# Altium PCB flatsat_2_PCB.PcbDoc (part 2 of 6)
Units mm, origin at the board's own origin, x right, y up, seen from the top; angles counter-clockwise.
Board outline 400 x 250 mm, 4 copper layers (Top Layer, FlatSat GND, FlatSat VCC, Bottom Layer), stack 2.102 mm thick; 196 components, 289 nets, 1724 pads, 1139 vias.
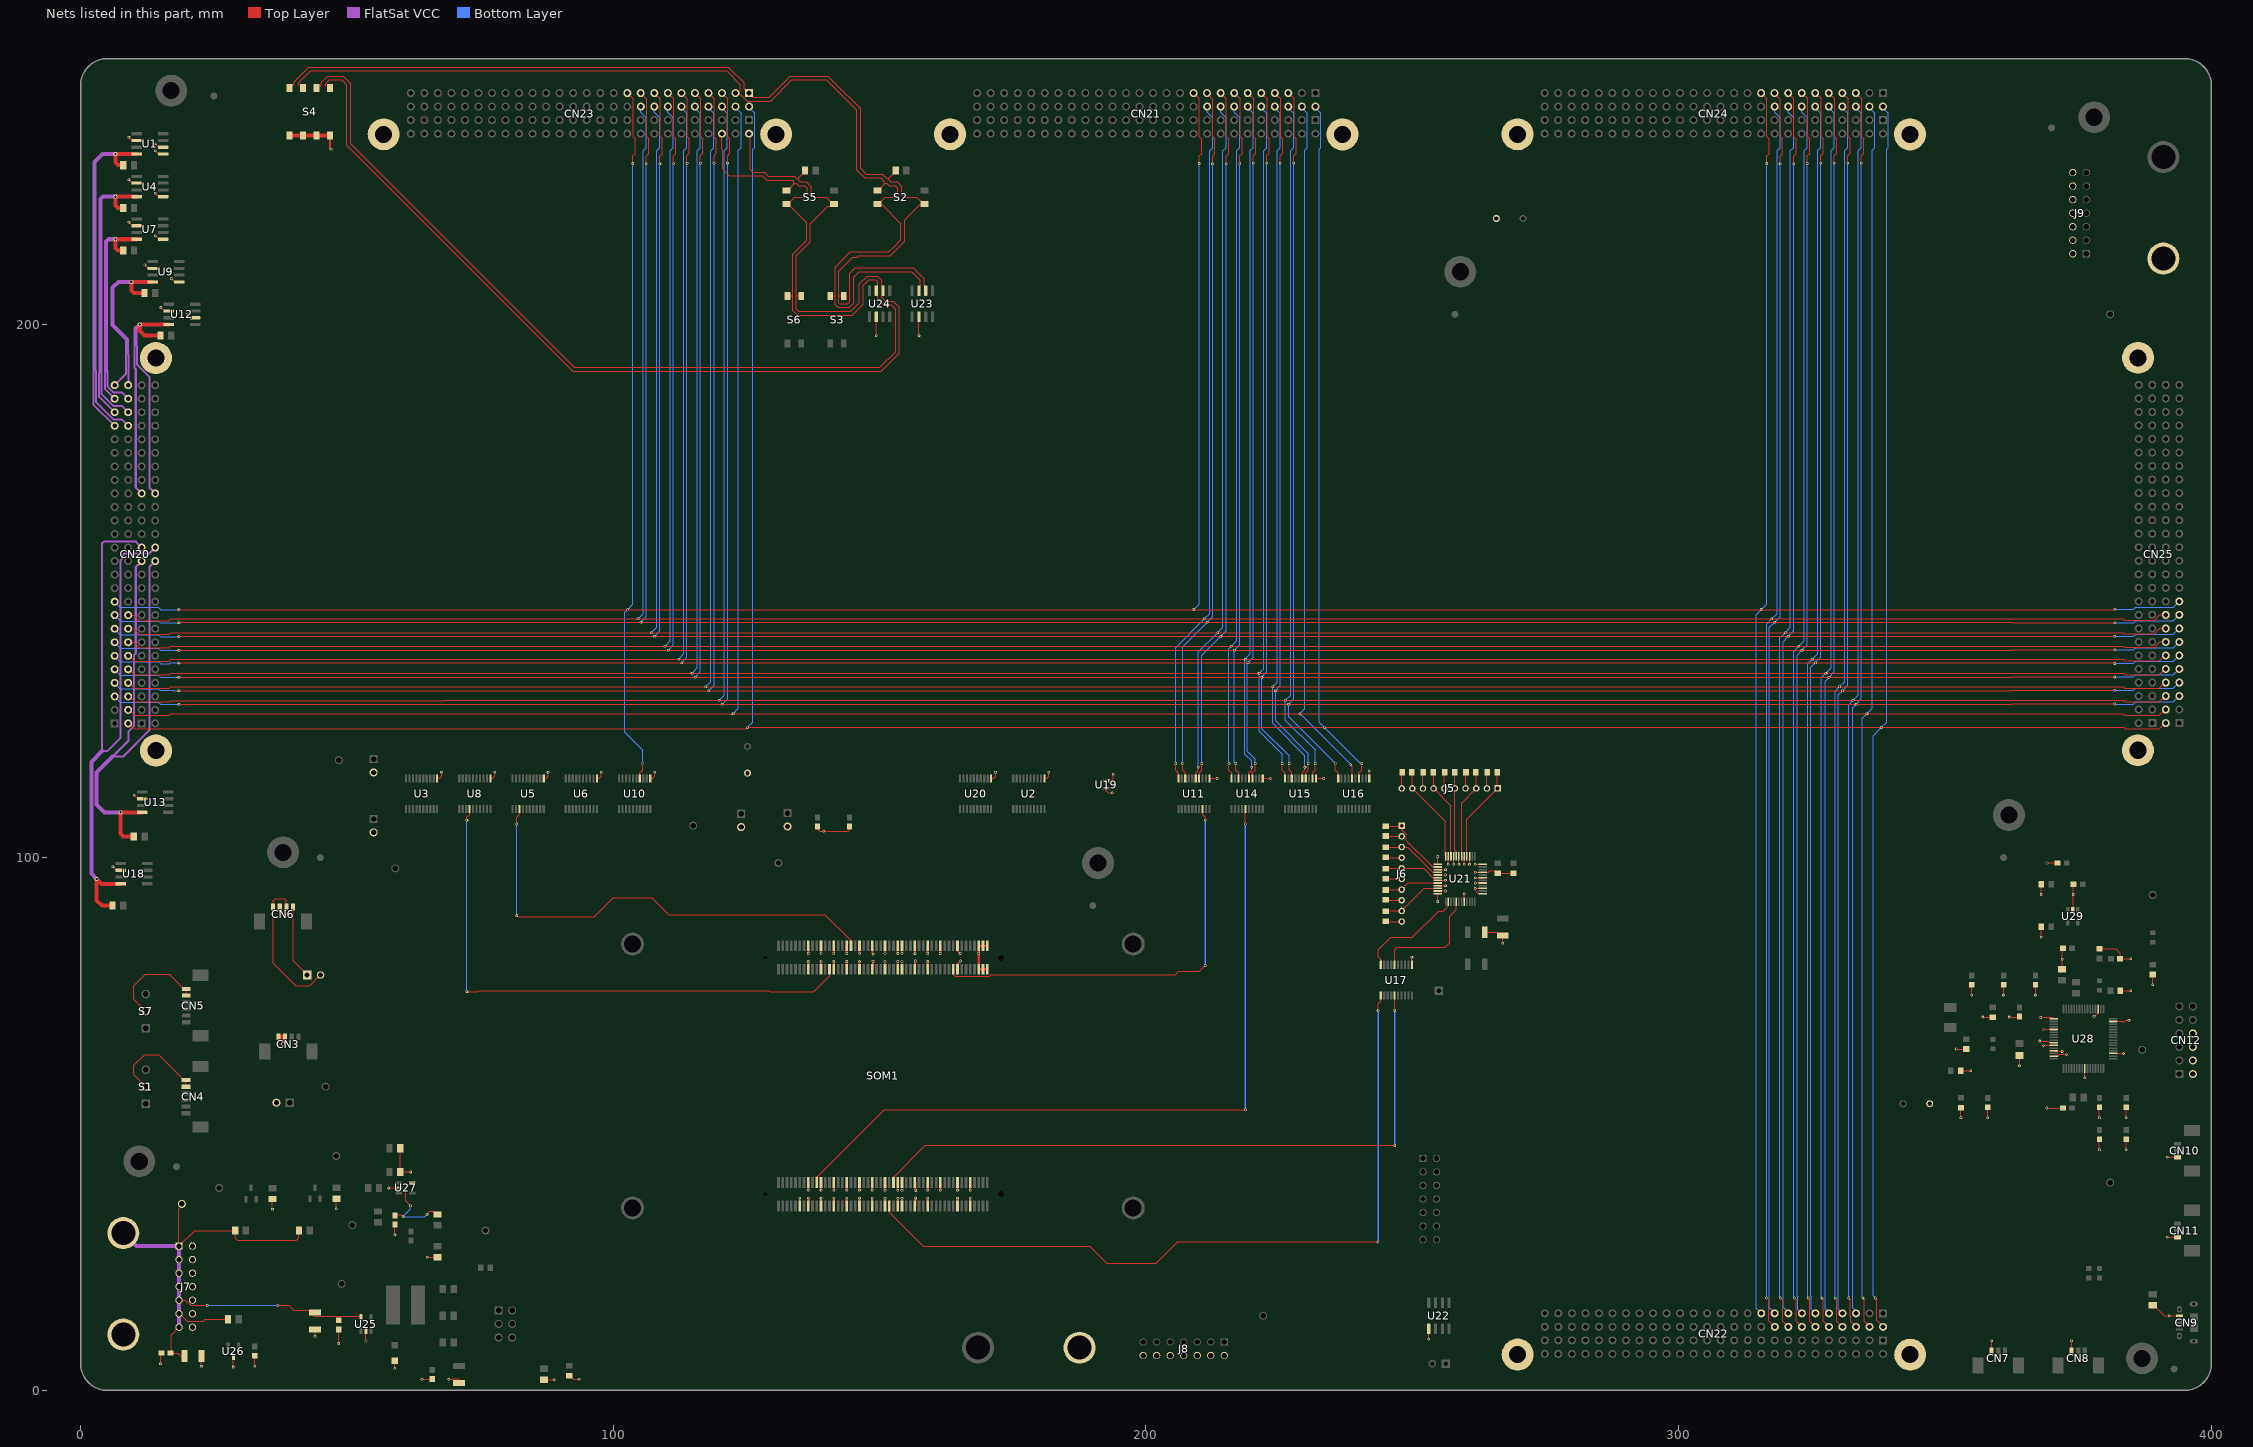
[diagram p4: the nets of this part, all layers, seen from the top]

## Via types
v1: diameter 0.508, hole 0.3, Top Layer to Bottom Layer, tented both sides, 1073 vias
v2: diameter 0.762, hole 0.45, Top Layer to Bottom Layer, tented both sides, 66 vias

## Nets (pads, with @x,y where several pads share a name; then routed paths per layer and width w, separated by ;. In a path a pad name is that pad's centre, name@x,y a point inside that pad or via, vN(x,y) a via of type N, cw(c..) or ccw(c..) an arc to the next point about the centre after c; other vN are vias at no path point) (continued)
5V: C1.1 C2.1 C6.1 C7.1 C9.2 CN1.1 J7.1 J7.3 J7.5 J7.7 J7.9 J7.11 J7.13 R2.2 R7.2 R10.2 R14.2 SOM1.JX1-57 SOM1.JX1-58 SOM1.JX1-59 SOM1.JX1-60 SOM1.JX2-12 SOM1.JX2-57 SOM1.JX2-58 SOM1.JX2-59 SOM1.JX2-60 TP4.1 U25.5 U27.5 | length 146.4
  Top Layer w0.203: J7.13@18.46,11.84 17,10.38 17,7.075 16.925,7 18.257,7 18.843,6.414 19.456,6.414 C2.1@19.468,6.427 ; J7.11@18.46,14.38 18.62,14.38 20,13 23,13 23.35,13.35 R14.2@27.654,13.35 ; J7.9@18.46,16.92 19.636,16.92 20.621,15.935 v1(23.754,15.935) ; TP4.1@19,35 19,34.649 18.46,34.109 J7.1@18.46,27.08 21.38,30 R2.2@28.984,30 28.984,28.596 29.415,28.165 40.501,28.165 40.984,28.648 R7.2@40.984,30 ; v1(36.935,15.935) 39.065,15.935 40,15 42.85,15 43.35,14.5 43.677,14.518 43.675,14.517 43.675,14.036 43.811,13.9 48.445,13.9 ; C6.1@48.445,13.15 48.445,13.9 ; U25.5@52.612,13.695 52.612,13.71 52.422,13.9 48.445,13.9 ; C9.2@59,32.85 59.075,32.925 60.196,32.925 v1(60.499,32.622) ; v1(61.917,34.653) 61,35.571 61,38.005 61.945,38.95 U27.5@62.255,38.95 ; v1(65,33) 65.575,33.575 66.175,33.575 66.236,33.514 66.502,33.514 R10.2@67,33.016 ; SOM1.JX2-12@135,34.6 v1(135,36.06) ; SOM1.JX2-58@153.4,34.6 v1(153.4,36.06) ; v1(153.4,37.54) SOM1.JX2-57@153.4,39 ; SOM1.JX1-58@153.4,79.05 v1(153.4,80.51) ; v1(153.4,81.99) SOM1.JX1-57@153.4,83.45 ; SOM1.JX2-60@154.2,34.6 v1(154.2,36.06) ; v1(154.2,37.54) SOM1.JX2-59@154.2,39 ; SOM1.JX1-60@154.2,79.05 v1(154.2,80.51) ; v1(154.2,81.99) SOM1.JX1-59@154.2,83.45
  FlatSat VCC w0.762: CN1.1@8,29.525 10.445,27.08 J7.1@18.46,27.08 J7.3@18.46,24.54 J7.5@18.46,22 J7.7@18.46,19.46 J7.9@18.46,16.92 J7.11@18.46,14.38 J7.13@18.46,11.84
  Bottom Layer w0.203: v1(23.754,15.935) v1(36.935,15.935) ; v1(61.917,34.653) 61.917,34.041 v1(60.499,32.622) 64.622,32.622 v1(65,33)
+RBF: CN6.2 CN6.4 J3.1 | length 17.6
  Top Layer w0.203: CN6.2@37.375,90.745 37.375,89.745 37.75,89.37 39.493,89.37 39.875,89.752 ; CN6.4@39.875,90.745 39.875,89.752 ; J3.1@42.5,78 39.875,80.625 39.875,89.752
-RBF: CN6.1 CN6.3 J3.2 | length 27.1
  Top Layer w0.203: CN6.3@38.625,90.745 38.625,91.957 38.286,92.296 36.517,92.296 36.125,91.904 CN6.1@36.125,90.745 36.125,80.225 40.35,76 43,76 J3.2@45,78
CAN_CHN_1_N: CN23.1 R16.1 S2.2B S3.2B S4.1B U23.6 | length 201.3
  Top Layer w0.203: S4.1B@39.19,244.45 39.19,244.65 39.638,245.098 39.985,245.098 40.104,245.217 40.104,245.68 42.855,248.431 121.575,248.431 124.566,245.44 124.566,244.307 124.685,244.188 124.832,244.188 CN23.1@125.48,243.54 126.128,242.892 126.128,242.86 126.247,242.741 129.271,242.741 133.241,246.711 140.289,246.711 142.896,244.104 145,242 146.413,240.587 146.413,229.413 147.492,228.334 150.494,228.334 151.403,227.425 151.571,227.425 151.807,227.661 ; S3.2B@143.27,205.45 142.475,205.45 ; R16.1@152.984,229 152.984,228.838 151.807,227.661 ; U23.6@158.635,206.47 158.635,207.155 158.356,207.434 158.356,208.65 156.295,210.711 145.4,210.711 144.404,209.715 144.404,204.404 144,204 142.475,204 142.356,204.119 142.356,205.331 142.475,205.45 ; 142.475,205.45 142.356,205.569 142.356,210.128 144.987,212.76 145.771,212.76 146.011,213 152.006,213 152.754,213.749 154.711,215.705 154.711,219.779 157.514,222.582 158.302,222.582 S2.2B@158.45,222.73 158.25,222.73 156.98,224 154.644,224 154.147,224.497 154.147,225.97 153.259,226.858 152.108,226.858 151.807,227.159 151.807,227.661
CAN_CHN_1_P: CN23.3 S2.1A S2.2A S3.1B S4.2B U23.7 | length 200.5
  Top Layer w0.203: S4.2B@41.73,244.45 41.73,244.65 41.282,245.098 40.935,245.098 40.816,245.217 40.816,245.386 43.149,247.719 121.281,247.719 123.854,245.146 123.854,243.949 123.694,243.788 123.188,243.788 CN23.3@122.94,243.54 123.188,243.292 123.833,243.292 125.095,242.03 129.565,242.03 133.536,246 139.994,246 142.185,243.81 144.246,241.749 145.702,240.293 145.702,229.118 145.91,228.91 147.197,227.623 150.199,227.623 150.9,226.922 150.9,226.42 ; S3.1B@140.73,205.45 141.525,205.45 ; S2.1A@149.55,225.27 149.75,225.27 150.9,226.42 ; U23.7@157.365,206.47 157.365,207.155 157.644,207.434 157.644,208.356 156,210 146.13,210 145.115,208.985 145.115,204.109 144.295,203.289 142.18,203.289 141.644,203.824 141.644,205.331 141.525,205.45 ; 141.525,205.45 141.644,205.569 141.644,210.858 144.497,213.711 151.711,213.711 152.707,214.707 154,216 154,219.034 150.486,222.548 149.732,222.548 S2.2A@149.55,222.73 149.75,222.73 151.02,224 152.644,224 153.436,224.792 153.436,225.675 152.965,226.147 151.814,226.147 151.304,226.656 151.136,226.656 150.9,226.42
CAN_CHN_2_N: CN23.54 R17.1 S4.4B S5.2B S6.2B U24.6 | length 230.1
  Top Layer w0.203: S4.4B@46.81,244.45 46.362,244.898 46.015,244.898 45.896,245.017 45.896,245.231 46.665,246 49,246 50,245 50,233.705 92.374,191.331 150.337,191.331 153.711,194.705 153.711,203.295 152.504,204.501 151.06,204.501 150.356,205.205 150.356,205.506 150.635,205.785 U24.6@150.635,206.47 150.635,207.155 150.356,207.434 150.356,208.374 149.541,209.189 147.628,209.189 146.208,207.769 146.208,204.208 144.54,202.54 134.815,202.54 134.356,203 134.356,205.331 134.475,205.45 ; CN23.54@125.48,235.92 125.704,235.696 125.704,235.059 125.74,235.023 125.74,229.26 126,229 126,228.83 126.119,228.711 128.295,228.711 129.127,227.879 133.949,227.879 134.403,227.425 134.571,227.425 134.807,227.661 ; S6.2B@135.27,205.45 134.475,205.45 ; R17.1@135.984,229 135.984,228.838 134.807,227.661 ; 134.475,205.45 134.356,205.569 134.356,213 137,215.644 137,219 140.282,222.282 141.002,222.282 S5.2B@141.45,222.73 141.25,222.73 139.98,224 137.644,224 137.147,224.497 137.147,225.97 136.259,226.858 135.108,226.858 134.807,227.159 134.807,227.661
CAN_CHN_2_P: CN23.58 S4.3B S5.1A S5.2A S6.1B U24.7 | length 232.6
  Top Layer w0.203: S4.3B@44.27,244.45 44.718,244.898 45.065,244.898 45.184,245.017 45.184,245.526 46.37,246.711 49.295,246.711 50.711,245.295 50.711,234 92.669,192.042 150.042,192.042 153,195 153,203 152.21,203.79 150.765,203.79 149.644,204.911 149.644,205.506 149.365,205.785 U24.7@149.365,206.175 ; CN23.58@120.4,235.92 120.4,233.004 120.537,232.868 120.537,229.26 121.797,228 128,228 128.832,227.168 133.654,227.168 133.9,226.922 133.9,226.42 ; S5.2A@132.55,222.73 S5.2A@132.75,222.73 ; S5.1A@132.55,225.27 132.75,225.27 133.9,226.42 ; S6.1B@132.73,205.45 133.525,205.45 ; U24.7@149.365,206.47 149.365,207.155 149.644,207.434 149.644,208.079 149.246,208.478 147.923,208.478 146.92,207.475 146.92,203.914 144.835,201.829 134.521,201.829 133.644,202.705 133.644,205.331 133.525,205.45 ; S5.2A@132.75,222.73 134.02,224 135.644,224 136.436,224.792 136.436,225.675 135.965,226.147 134.814,226.147 134.304,226.656 134.136,226.656 133.9,226.42 ; S5.2A@132.75,222.73 136.289,219.191 136.289,215.939 133.644,213.295 133.644,205.569 133.525,205.45
CH1: C19.2 J5.1 U21.16 | length 18.2
  Top Layer w0.203: U21.16@260.25,100.25 260.25,107.25 J5.1@266,113 265.925,113.075 C19.2@265.925,116
CH3: C20.2 J5.3 U21.18 | length 16.9
  Top Layer w0.203: U21.18@259.25,100.25 259.25,110.25 J5.3@262,113 262,115.925 C20.2@261.925,116
CH5: C21.2 J5.5 U21.20 | length 15.9
  Top Layer w0.203: C21.2@257.925,116 258,115.925 J5.5@258,113 258,101.402 258.25,101.152 U21.20@258.25,100.25
CH7: C22.2 J5.7 U21.22 | length 17.1
  Top Layer w0.203: C22.2@253.925,116 254,115.925 J5.7@254,113 257.25,109.75 U21.22@257.25,100.25
CH9: C23.2 J5.9 U21.24 | length 18.4
  Top Layer w0.203: C23.2@249.925,116 250,115.925 J5.9@250,113 256.148,106.852 256.148,100.352 U21.24@256.25,100.25
CH11: C24.2 J6.1 U21.26 | length 14.1
  Top Layer w0.203: C24.2@245,105.925 247.925,105.925 J6.1@248,106 248,105.257 248.889,104.368 248.889,103.209 253.848,98.25 U21.26@254.75,98.25
CH13: C25.2 J6.3 U21.28 | length 11.7
  Top Layer w0.203: C25.2@245,101.925 245.075,102 J6.3@248,102 249.098,102 253.848,97.25 U21.28@254.75,97.25
CH15: C26.2 J6.5 U21.30 | length 10.5
  Top Layer w0.203: C26.2@245,97.925 245.075,98 J6.5@248,98 252.098,98 253.848,96.25 U21.30@254.75,96.25
CH17: C27.2 J6.7 U21.32 | length 10.3
  Top Layer w0.203: C27.2@245,93.925 245.075,94 J6.7@248,94 249.25,95.25 U21.32@254.75,95.25
CH19: C28.2 J6.9 U21.34 | length 11.5
  Top Layer w0.203: C28.2@245,89.925 245.075,90 J6.9@248,90 252.25,94.25 U21.34@254.75,94.25
CLK_CHN_1: SOM1.JX1-35 U5.3 | length 89
  Top Layer w0.203: v1(81.868,106.321) 81.868,107.579 82.375,108.087 U5.3@82.375,109.13 ; v1@81.902,89.129 82.15,88.88 96.407,88.88 100.006,92.479 107.214,92.479 110.386,89.307 139.735,89.307 144.385,84.657 144.6,84.657 SOM1.JX1-35@144.6,83.45
  Top Layer w0.381: v1(81.868,89.129) v1@81.902,89.129
  Bottom Layer w0.203: v1(81.868,89.129) v1(81.868,106.321)
CLK_CHN_2: SOM1.JX2-19 U14.5 | length 143.3
  Top Layer w0.203: SOM1.JX2-19@138.2,39 138.2,40.207 138.415,40.207 150.891,52.683 v1(218.675,52.683) ; v1(218.675,106.321) U14.5@218.675,109.13
  Bottom Layer w0.279: v1(218.675,52.683) v1(218.675,106.321)
CLK_CHN_3: SOM1.JX2-54 U17.1 | length 145.1
  Top Layer w0.203: SOM1.JX2-54@151.8,34.6 151.8,33.394 151.809,33.394 158.136,27.066 189.42,27.066 192.636,23.851 201.966,23.851 205.966,27.851 v1(243.568,27.851) ; v1(243.568,71.321) 243.568,72.579 244.075,73.087 U17.1@244.075,74.13
  Bottom Layer w0.279: v1(243.568,27.851) v1(243.568,71.321)
CLK_SENSORS: U17.20 U21.38 | length 20.5
  Top Layer w0.203: U17.20@244.075,79.87 244.075,80.913 243.568,81.421 243.568,82.679 245.905,85.017 250.017,85.017 254.957,89.957 255.803,89.957 256.702,90.856 256.702,91.702 U21.38@256.75,91.75
COMMON_KILL_SWITCH_1: CN4.5 CN4.6 S1.2 | length 18.7
  Top Layer w0.203: S1.2@12.245,57 10,59.245 10,61 12,63 14.64,63 19.374,58.266 CN4.6@19.774,58.266 CN4.5@19.774,57.016
COMMON_KILL_SWITCH_2: CN5.5 CN5.6 S7.2 | length 18.8
  Top Layer w0.203: S7.2@12.239,71.2 10,73.439 10,76 12.125,78.125 16.621,78.125 19.38,75.366 CN5.6@19.78,75.366 CN5.5@19.78,74.116
CS_CHN_1: SOM1.JX1-26 U8.4 | length 105.2
  Top Layer w0.203: v1(72.518,107.006) 72.518,107.579 73.025,108.087 U8.4@73.025,109.13 ; v1@72.552,74.807 72.615,74.87 74.423,74.87 74.601,75.048 129.258,75.048 129.436,74.87 137.618,74.87 140.591,77.844 140.6,77.844 SOM1.JX1-26@140.6,79.05
  Top Layer w0.381: v1(72.518,74.807) v1@72.552,74.807
  Bottom Layer w0.203: v1(72.518,74.807) v1(72.518,107.006)
CS_CHN_2: SOM1.JX1-84 U11.8 | length 78.8
  Top Layer w0.203: SOM1.JX1-84@163.8,79.05 163.952,78.898 163.952,78.032 164.23,77.754 170.57,77.754 170.815,78 205.461,78 206.121,78.66 210.03,78.66 v1(211.132,79.762) ; U11.8@210.625,109.13 210.625,108.087 211.132,107.579 v1(211.132,107.006)
  Bottom Layer w0.279: v1(211.132,79.762) v1(211.132,107.006)
CS_CHN_3: SOM1.JX2-55 U17.5 | length 125.8
  Top Layer w0.203: SOM1.JX2-55@152.6,39 152.6,40.207 152.815,40.207 158.583,45.975 v1(246.675,45.975) ; v1(246.675,71.321) U17.5@246.675,74.13
  Bottom Layer w0.279: v1(246.675,45.975) v1(246.675,71.321)
CS_SENSORS: U17.16 U21.41 | length 21.9
  Top Layer w0.203: U17.16@246.675,79.87 246.675,82.679 246.996,83 247,83 247.212,83.212 256.212,83.212 257,84 257,89 258.25,90.25 U21.41@258.25,91.75
EPS_H1-45: CN20.45 CN20.46 R25.1 U1.8 | length 77.2
  Top Layer w0.762: R25.1@7.984,230 7,230 6.53,230.47 v2(6.53,232.095) U1.8@10.53,232.095
  FlatSat VCC w0.381: CN20.45@6.38,181.08 2.401,185.059 2.401,191.493 2.635,191.726 2.862,191.499 2.862,185.556 6.193,182.225 7.775,182.225 CN20.46@8.92,181.08
  FlatSat VCC w0.762: 2.635,191.726 2.635,230.635 4.095,232.095 v2(6.53,232.095)
EPS_H1-47: CN20.47 CN20.48 R27.1 U4.8 | length 62.3
  Top Layer w0.762: R27.1@7.984,222 7,222 6.53,222.47 v2(6.53,224.095) U4.8@10.53,224.095
  FlatSat VCC w0.381: CN20.47@6.38,183.62 3.478,186.522 3.478,191.001 3.711,191.235 3.946,191 3.946,187.012 6.193,184.765 7.775,184.765 CN20.48@8.92,183.62
  FlatSat VCC w0.762: 3.711,191.235 3.711,223.649 4.158,224.095 v2(6.53,224.095)
EPS_H1-49: CN20.49 CN20.50 R26.1 U7.8 | length 47.6
  Top Layer w0.762: R26.1@7.984,214 7,214 6.53,214.47 v2(6.53,216.095) U7.8@10.53,216.095
  FlatSat VCC w0.381: CN20.49@6.38,186.16 4.524,188.016 4.524,191.315 4.77,191.561 4.998,191.333 4.994,191.33 4.994,188.504 6.193,187.305 7.775,187.305 CN20.50@8.92,186.16
  FlatSat VCC w0.762: 4.77,191.561 4.77,215.649 5.217,216.095 v2(6.53,216.095)
EPS_H1-51: CN20.51 CN20.52 R28.1 U9.8 | length 38.8
  Top Layer w0.762: R28.1@11.984,206 10,206 9.53,206.47 v2(9.53,208.095) U9.8@13.53,208.095
  FlatSat VCC w0.381: CN20.51@6.38,188.7 8.511,190.831 8.502,190.841 8.502,194.485 8.735,194.719 8.963,194.491 8.963,188.743 CN20.52@8.92,188.7
  FlatSat VCC w0.762: 8.735,194.719 8.735,197.265 6,200 6,207 7.095,208.095 v2(9.53,208.095)
EPS_H2-25: CN20.77 CN20.78 R30.1 U13.8 | length 106.2
  Top Layer w0.762: R30.1@9.984,104 8,104 7.482,104.518 v2(7.482,108.518) U13.8@11.53,108.518
  FlatSat VCC w0.381: CN20.77@11.46,155.68 10.341,154.561 10.341,138.368 10.039,138.065 10.039,124.737 9,123.698 9,122 6,119 8,119 12.881,123.881 12.881,154.561 CN20.78@14,155.68
  FlatSat VCC w0.762: 6,119 3,116 3,110 4.482,108.518 v2(7.482,108.518)
EPS_H2-27: CN20.79 CN20.80 R31.1 U18.8 | length 130.3
  Top Layer w0.762: R31.1@5.984,91 4,91 3,92 v2(3,96) 3.905,95.095 U18.8@7.53,95.095
  FlatSat VCC w0.381: CN20.79@11.46,158.22 10.341,159.339 4.339,159.339 4,159 4,120 5,120 7.499,122.499 7.499,155.84 7.867,156.208 7.867,156.733 8.235,157.101 12.881,157.101 CN20.80@14,158.22
  FlatSat VCC w0.762: v2(3,96) 2,97 2,118 4,120
EPS_H2-35: CN20.87 CN20.88 R29.1 U12.8 | length 73
  Top Layer w0.762: R29.1@14.984,198 12,198 11.095,198.905 v2(11.095,200.095) U12.8@16.53,200.095
  FlatSat VCC w0.381: CN20.87@11.46,168.38 10.341,169.499 10.341,191.714 10.085,191.971 10.085,196.075 10.318,196.309 10.546,196.082 10.546,192.606 12.881,190.27 12.881,169.499 CN20.88@14,168.38
  FlatSat VCC w0.762: 10.318,196.309 10.318,199.318 v2(11.095,200.095)
GND: C1.2 C2.2 C4.2 C5.2 C6.2 C7.2 C8.1 C9.1 C11.2 C12.2 C13.2 C14.2 C15.2 C17.2 C18.2 C19.1 C20.1 C21.1 C22.1 C23.1 C24.1 C25.1 C26.1 C27.1 C28.1 C29.2 C30.2 C31.2 C32.2 C33.2 C34.2 C35.2 C36.2 C37.2 C38.2 C39.2 C40.1 C41.1 C42.2 C43.2 C44.2 C45.2 C46.2 C47.2 C48.2 C49.2 C50.2 C51.2 CN1.0 CN2.0 CN3.1 CN3.2 CN7.1 CN8.1 CN9.5 CN10.1 CN11.1 CN12.7 CN12.8 CN12.9 CN12.10 CN13.0 CN15.2 CN16.2 CN17.2 CN18.2 CN19.2 CN20.0 CN21.0 CN22.0 CN23.0 CN24.0 CN25.0 D1.2 J5.2 J5.4 J5.6 J5.8 J5.10 J6.2 J6.4 J6.6 J6.8 J6.10 J7.2 J7.4 J7.6 J7.8 J7.10 J7.12 J7.14 J8.2 J8.4 J8.6 J8.8 J8.10 J8.12 J8.14 J9.2 J9.4 J9.6 J9.8 J9.10 J9.12 J9.14 L2.1 L3.1 L4.1 R3.1 R6.1 R8.1 R12.2 R13.1 R15.1 R19.1 R21.1 R23.2 S4.1A S4.2A S4.3A S4.4A SOM1.JX1-15 SOM1.JX1-16 SOM1.JX1-21 SOM1.JX1-22 SOM1.JX1-27 SOM1.JX1-28 SOM1.JX1-33 SOM1.JX1-34 SOM1.JX1-39 SOM1.JX1-40 SOM1.JX1-45 SOM1.JX1-46 SOM1.JX1-51 SOM1.JX1-52 SOM1.JX1-65 SOM1.JX1-66 SOM1.JX1-71 SOM1.JX1-72 SOM1.JX1-77 SOM1.JX1-85 SOM1.JX1-86 SOM1.JX1-95 SOM1.JX1-96 SOM1.JX1-97 SOM1.JX1-98 SOM1.JX1-99 SOM1.JX1-100 SOM1.JX2-15 SOM1.JX2-16 SOM1.JX2-21 SOM1.JX2-22 SOM1.JX2-27 SOM1.JX2-28 SOM1.JX2-33 SOM1.JX2-34 SOM1.JX2-39 SOM1.JX2-40 SOM1.JX2-45 SOM1.JX2-46 SOM1.JX2-51 SOM1.JX2-52 SOM1.JX2-65 SOM1.JX2-66 SOM1.JX2-71 SOM1.JX2-72 SOM1.JX2-77 SOM1.JX2-85 SOM1.JX2-86 SOM1.JX2-91 SOM1.JX2-92 U1.1 U1.2 U1.6 U2.11 U3.11 U4.1 U4.6 U5.11 U6.11 U7.1 U7.6 U8.11 U9.1 U9.6 U10.11 U11.11 U12.2 U12.6 U13.6 U14.11 U15.11 U16.11 U17.11 U18.6 U19.2 U19.4 U20.11 U21.1 U21.3 U21.5 U21.7 U21.9 U21.12 U21.15 U21.17 U21.19 U21.21 U21.23 U21.25 U21.27 U21.29 U21.31 U21.33 U21.35 U21.36 U21.44 U22.5 U23.2 U24.2 U25.2 U26.3 U27.2 U28.1 U28.5 U28.10 U28.11 U28.13 U28.15 U28.25 U28.35 U28.47 U28.51 U29.2 | length 350.3
  Top Layer w0.203: v1(6.06,98.27) 6.695,97.635 U18.6@7.53,97.635 ; v1(9.06,219.27) 9.695,218.635 U7.6@10.53,218.635 ; v1(9.06,227.27) 9.695,226.635 U4.6@10.53,226.635 ; v1(9.06,235.27) 9.695,234.635 U1.6@10.53,234.635 ; v1(10.06,111.693) 10.695,111.058 U13.6@11.53,111.058 ; v1(12.06,211.27) 12.695,210.635 U9.6@13.53,210.635 ; v1(14,216.73) 14.635,216.095 U7.1@15.47,216.095 ; v1(14,224.73) 14.635,224.095 U4.1@15.47,224.095 ; v1(14,232.73) 14.635,232.095 U1.1@15.47,232.095 ; v1(14,234) 14.635,233.365 U1.2@15.47,233.365 ; v1(15,5) 15,6.925 C1.2@15.075,7 ; v1(15.06,203.27) 15.695,202.635 U12.6@16.53,202.635 ; v1(17,208.73) 17.635,208.095 U9.1@18.47,208.095 ; v1(20,202) 20.635,201.365 U12.2@21.47,201.365 ; v1(22.668,4.502) C2.2@22.668,6.427 ; v1(28.67,4.37) U26.3@28.67,6.295 ; v1(32.67,4.5) C11.2@32.67,6.5 ; v1(36,34.004) R3.1@36,35.929 ; CN3.1@36.827,66.077 CN3.1@37.125,66.375 ; v1(44,10.15) C7.2@44,11.4 ; v1(48,34.075) R8.1@48,35.984 R8.1@48,36 ; v1(48.445,8.775) C6.2@48.445,11.45 ; v1(53.562,9.26) U25.2@53.562,11.185 ; v1(57.82,38) U27.2@59.745,38 ; v1(58.945,4.125) D1.2@58.945,6.05 ; v1(59,29.15) C9.1@59,31.15 ; R12.2@60.016,45.44 R15.1@60.016,41 v1(61.941,41) ; v1(64.075,2.075) 65.925,2.075 C4.2@66,2.15 ; v1(65.075,24.984) R13.1@67,24.984 ; U3.11@66.925,114.87 67.378,114.87 67.754,115.246 v1(67.754,116.046) ; v1(69.12,2.075) 69.82,2.075 69.945,2.2 70.8,2.2 71,2 71,1.445 C5.2@71.045,1.4 ; U8.11@76.925,114.87 77.378,114.87 77.754,115.246 v1(77.754,116.046) ; U5.11@86.925,114.87 87.378,114.87 87.754,115.246 v1(87.754,116.046) ; R6.1@87,1.984 v1(88.925,1.984) ; C8.1@91.691,2.775 91.766,2.775 92.366,2.175 92.441,2.1 v1(93.616,2.1) ; U6.11@96.925,114.87 97.378,114.87 97.754,115.246 v1(97.754,116.046) ; U10.11@106.925,114.87 107.378,114.87 107.754,115.246 v1(107.754,116.046) ; C13.2@138.33,105.85 138.353,105.827 138.353,105.299 138.706,104.946 v1(139.506,104.946) 139.56,105 144.208,105 144.33,105.123 C12.2@144.33,105.775 ; v1(149.365,198) U24.2@149.365,201.53 ; v1(157.365,198) U23.2@157.365,201.53 ; U20.11@170.925,114.87 171.378,114.87 171.754,115.246 v1(171.754,116.046) ; U2.11@180.925,114.87 181.378,114.87 181.754,115.246 v1(181.754,116.046) ; U19.2@192.5,113 192.5,112.547 192.876,112.171 v1(193.676,112.171) ; U19.4@193,114.47 193.453,114.47 193.829,114.846 v1(193.829,115.646) ; U11.11@211.925,114.87 v1(213.385,114.87) ; U14.11@221.925,114.87 v1(223.385,114.87) ; U15.11@231.925,114.87 v1(233.385,114.87) ; U16.11@241.925,114.87 v1(241.925,116.33) ; C28.1@245,88.075 245.075,88 J6.10@248,88 ; C27.1@245,92.075 245.075,92 J6.8@248,92 ; C26.1@245,96.075 245.075,96 J6.6@248,96 ; C25.1@245,100.075 245.075,100 J6.4@248,100 ; C24.1@245,104.075 245.075,104 J6.2@248,104 ; J5.10@248,113 248,115.925 C23.1@248.075,116 ; U17.11@249.925,79.87 v1(249.925,81.33) ; J5.8@252,113 252,115.925 C22.1@252.075,116 ; v1(253.095,9.6) U22.5@253.095,11.525 ; v1(254.75,91.79) U21.36@254.75,93.25 ; U21.35@254.75,93.75 v1(256.21,93.75) ; U21.33@254.75,94.75 v1(256.21,94.75) ; U21.31@254.75,95.75 v1(256.21,95.75) ; U21.29@254.75,96.75 v1(256.21,96.75) ; U21.27@254.75,97.75 v1(256.21,97.75) ; U21.25@254.75,98.75 v1(254.75,100.21) ; J5.6@256,113 256,115.925 C21.1@256.075,116 ; v1(256.75,98.79) U21.23@256.75,100.25 ; v1(257.75,98.79) U21.21@257.75,100.25 ; v1(258.75,98.79) U21.19@258.75,100.25 ; U21.44@259.75,91.75 v1(259.75,93.21) ; v1(259.75,98.79) U21.17@259.75,100.25 ; J5.4@260,113 260,115.925 C20.1@260.075,116 ; v1(260.75,98.79) U21.15@260.75,100.25 ; v1@261.747,94.208 261.772,94.182 261.772,93.849 262.323,93.298 263.202,93.298 U21.1@263.25,93.25 ; v1(261.79,94.25) U21.3@263.25,94.25 ; v1(261.79,95.25) U21.5@263.25,95.25 ; v1(261.79,96.25) U21.7@263.25,96.25 ; v1(261.79,97.25) U21.9@263.25,97.25 264.29,97.25 264.537,97.497 265.578,97.497 C15.2@266,97.075 C14.2@269,97.075 ; v1(261.79,98.75) U21.12@263.25,98.75 ; C18.2@263.6,86 265.85,86 266.45,85.4 C17.2@267,85.4 v1(267,83.94) ; J5.2@264,113 264,115.925 C19.1@264.075,116 ; v1(352.075,64.075) C40.1@354,64.075 ; C41.1@352.925,60 v1(354.85,60) ; v1(353,51.15) C35.2@353,53.075 ; v1(355,74.15) C51.2@355,76.15 ; v1(357.075,70.075) C37.2@359,70.075 ; v1(358,51.15) C34.2@358,53.15 ; CN7.1@358.75,7.375 v1(358.75,9.3) ; v1(361,74.15) C50.2@361,76.15 ; v1(362.075,70.075) 363.925,70.075 C38.2@364,70.15 ; v1(364,60.932) R19.1@364,62.857 ; v1(367,74.15) C49.2@367,76.15 ; v1(367.79,65.569) 369.324,65.569 369.572,65.32 370.355,65.32 U28.10@370.425,65.25 ; v1(368,70) 370.175,70 U28.1@370.425,69.75 ; v1(368.075,85.075) C48.2@368.075,87 ; v1(368.075,93.075) C33.2@368.075,95 ; v1(368.5,64.75) U28.11@370.425,64.75 ; v1(368.5,67.75) U28.5@370.425,67.75 ; v1(369.075,53) C39.2@372.15,53 ; v1(369.15,99) C32.2@371.15,99 ; U28.15@370.425,62.75 370.495,62.82 371.278,62.82 371.515,63.058 v1(372.802,63.058) ; U28.13@370.425,63.75 370.495,63.68 371.945,63.68 v1(371.998,63.627) ; R23.2@372,79.016 v1(372,80.941) 372,82.925 C36.2@372.075,83 ; CN8.1@373.75,7.375 v1(373.75,9.3) ; U29.2@374,90.2 374.075,90.275 v1(374.075,93.075) 374.075,94.925 C46.2@374.15,95 ; U28.25@376.25,60.425 376.255,60.42 v1(376.255,58.676) ; v1(377.979,70.235) 378.038,70.293 378.25,70.293 378.731,70.774 378.731,71.556 U28.51@378.75,71.575 ; v1(379,45.15) C43.2@379,47.15 ; v1(379,51.15) C45.2@379,53.15 ; C30.2@379,82.925 382.075,82.925 382.925,82.075 382.925,81.075 C29.2@382.85,81 v1(384.85,81) ; U28.35@381.575,63.25 v1(383.5,63.25) ; U28.47@381.575,69.25 383.24,69.25 383.274,69.216 383.716,69.216 383.967,69.468 v1(384.529,69.468) ; C47.2@382.925,75 v1(384.85,75) ; v1(384,45.15) C42.2@384,47.15 ; v1(384,51.15) C44.2@384,53.15 ; R21.1@389,15.984 389.162,15.984 391.146,14 v1(392.075,14) CN9.5@394,14 ; v1(389,76.15) C31.2@389,78.075 ; v1(391.7,28.75) CN11.1@393.625,28.75 ; v1(391.7,43.75) CN10.1@393.625,43.75
  Top Layer w0.381: S4.4A@46.81,235.55 46.81,233.19 v1(47,233) ; SOM1.JX2-16@136.6,34.6 v1(136.6,36.047) ; v1(136.6,37.553) SOM1.JX2-15@136.6,39 ; SOM1.JX1-16@136.6,79.05 v1(136.6,80.497) ; v1(136.6,82.003) SOM1.JX1-15@136.6,83.45 ; SOM1.JX2-22@139,34.6 v1(139,36.047) ; v1(139,37.553) SOM1.JX2-21@139,39 ; SOM1.JX1-22@139,79.05 v1(139,80.497) ; v1(139,82.003) SOM1.JX1-21@139,83.45 ; SOM1.JX2-28@141.4,34.6 v1(141.4,36.047) ; v1(141.4,37.553) SOM1.JX2-27@141.4,39 ; SOM1.JX1-28@141.4,79.05 v1(141.4,80.497) ; v1(141.4,82.003) SOM1.JX1-27@141.4,83.45 ; SOM1.JX2-34@143.8,34.6 v1(143.8,36.047) ; v1(143.8,37.553) SOM1.JX2-33@143.8,39 ; SOM1.JX1-34@143.8,79.05 v1(143.8,80.497) ; v1(143.8,82.003) SOM1.JX1-33@143.8,83.45 ; SOM1.JX2-40@146.2,34.6 v1(146.2,36.047) ; v1(146.2,37.553) SOM1.JX2-39@146.2,39 ; SOM1.JX1-40@146.2,79.05 v1(146.2,80.497) ; v1(146.2,82.003) SOM1.JX1-39@146.2,83.45 ; SOM1.JX2-46@148.6,34.6 v1(148.6,36.047) ; v1(148.6,37.553) SOM1.JX2-45@148.6,39 ; SOM1.JX1-46@148.6,79.05 148.747,79.197 v1(148.747,80.533) ; SOM1.JX1-45@148.6,83.45 148.663,83.386 148.663,82.036 148.78,81.92 v1(148.78,81.886) ; SOM1.JX2-52@151,34.6 v1(151,36.047) ; v1(151,37.553) SOM1.JX2-51@151,39 ; SOM1.JX1-52@151,79.05 v1(151,80.497) ; v1(151,82.003) SOM1.JX1-51@151,83.45 ; SOM1.JX2-66@156.6,34.6 156.757,34.757 v1(156.757,36.119) ; SOM1.JX2-65@156.6,39 156.596,38.996 156.768,38.823 v1(156.768,37.532) ; SOM1.JX1-66@156.6,79.05 156.665,79.115 v1(156.665,80.607) ; SOM1.JX1-65@156.6,83.45 156.652,83.398 v1(156.652,81.951) ; SOM1.JX2-72@159,34.6 v1(159,36.047) ; v1(159,37.553) SOM1.JX2-71@159,39 ; SOM1.JX1-72@159,79.05 v1(159,80.497) ; v1(159,82.003) SOM1.JX1-71@159,83.45 ; v1(161.4,37.553) SOM1.JX2-77@161.4,39 ; v1(161.4,82.003) SOM1.JX1-77@161.4,83.45 ; SOM1.JX2-86@164.6,34.6 v1(164.6,36.047) ; v1(164.6,37.553) SOM1.JX2-85@164.6,39 ; SOM1.JX1-85@164.6,83.45 164.663,83.387 164.663,82.395 165.035,82.024 165.115,82.024 v1(165.139,82) ; SOM1.JX1-86@164.663,79.114 164.663,80.105 v1@165.034,80.476 ; SOM1.JX2-92@167,34.6 v1(167,36.047) ; v1(167,37.553) SOM1.JX2-91@167,39 ; SOM1.JX1-100@170.2,79.05 SOM1.JX1-98@169.4,79.05 SOM1.JX1-96@168.6,79.05 v1(168.6,82.003) SOM1.JX1-95@168.6,83.45 SOM1.JX1-97@169.4,83.45 SOM1.JX1-99@170.2,83.45
  Top Layer w0.762: CN3.1@37.125,66.375 CN3.2@38.375,66.375 38.356,66.356 38.356,65.356 v2(38,65) ; S4.1A@39.19,235.55 S4.2A@41.73,235.55 S4.3A@44.27,235.55 S4.4A@46.81,235.55
  other v1: 165.164,80.604
H1-2: CN20.2 CN21.2 CN22.2 CN23.2 CN24.2 CN25.2 U16.14 | length 862.6
  Top Layer w0.203: CN20.2@9.1,125.2 10.13,124.17 124.906,124.17 v1(125.183,124.447) v1(233.503,124.447) v1(338.043,124.447) 383.54,124.447 383.762,124.225 390.236,124.225 CN25.2@391.265,125.255 ; U16.14@239.975,114.87 239.975,115.913 240.482,116.421 v1(240.482,117.679) ; v1(336.92,17.333) 336.958,17.333 337.229,17.062 337.229,13.111 338.368,11.972 CN22.2@338.368,11.923
  Bottom Layer w0.203: v1(125.183,124.447) 126.183,125.447 126.183,232.99 126.51,233.316 126.51,239.79 125.48,240.82 CN23.2@125.48,241 ; CN21.2@231.8,241 231.8,240.82 232.83,239.79 232.83,233.316 232.503,232.99 232.503,125.447 v1(233.503,124.447) 240.213,117.737 240.424,117.737 v1(240.482,117.679) ; v1(336.92,17.333) 336.504,17.75 336.504,122.908 v1(338.043,124.447) 339.043,125.447 339.043,232.99 339.37,233.316 339.37,239.79 338.34,240.82 CN24.2@338.34,241
H1-4: CN20.4 CN21.4 CN22.4 CN23.4 CN24.4 CN25.4 U16.16 | length 860.1
  Top Layer w0.203: CN20.4@9.1,127.74 10.13,126.71 16.604,126.71 16.923,127.03 v1(122.481,127.03) v1(228.885,127.03) v1(335.341,127.03) 383.497,127.03 383.762,126.765 390.236,126.765 CN25.4@391.265,127.795 ; v1(238.456,117.46) 238.53,117.46 238.675,117.315 U16.16@238.675,114.87 ; v1(334.591,17.349) 334.591,17.267 334.799,17.059 334.799,13.945 334.8,13.944 334.8,13 335.828,11.972 CN22.4@335.828,11.923
  Bottom Layer w0.203: v1(122.481,127.03) 123.481,128.03 123.481,232.828 123.97,233.316 123.97,239.79 CN23.4@122.94,240.82 ; CN21.4@229.26,240.82 230.29,239.79 230.29,233.316 229.801,232.828 229.801,128.03 229.801,127.946 v1(228.885,127.03) 228.96,127.03 238.456,117.534 v1(238.456,117.46) ; v1(334.591,17.349) 334.566,17.349 334.447,17.468 334.447,36 334.447,126.136 v1(335.341,127.03) 336.341,128.03 336.341,232.828 336.83,233.316 336.83,239.79 CN24.4@335.8,240.82
H1-5: CN20.5 CN21.5 CN22.5 CN23.5 CN24.5 CN25.5 U16.20 | length 869.4
  Top Layer w0.203: v1(18.478,128.793) v1(120.444,128.793) v1(226.764,128.793) v1(333.304,128.793) 362.403,128.793 362.514,128.904 381.831,128.904 v1(381.887,128.848) ; CN23.5@120.4,243.54 121.49,242.45 121.49,235.319 121.887,234.923 121.887,232.232 121.444,231.789 v1(121.444,230.364) ; CN21.5@226.72,243.54 227.81,242.45 227.81,235.319 228.207,234.923 228.207,232.232 227.764,231.789 v1(227.764,230.364) ; v1(235.567,117.678) 235.568,116.421 236.075,115.913 U16.20@236.075,114.87 ; CN24.5@333.26,243.54 334.35,242.45 334.35,235.319 334.747,234.923 334.747,232.232 334.304,231.789 v1(334.304,230.364)
  Bottom Layer w0.203: CN20.5@6.38,130.28 7.47,129.19 14.601,129.19 14.997,128.793 v1(18.478,128.793) ; v1(120.444,128.793) 121.444,129.793 v1(121.444,230.364) ; v1(227.764,230.364) 227.764,129.793 v1(226.764,128.793) 226.764,126.482 234.246,119 v1(235.567,117.678) ; CN22.5@333.288,14.463 333.04,14.711 333.04,15.19 332.69,15.54 332.69,128.179 v1(333.304,128.793) 334.304,129.793 v1(334.304,230.364) ; v1(381.887,128.848) 385.368,128.848 385.765,129.245 392.895,129.245 CN25.5@393.985,130.335
H1-6: CN20.6 CN21.6 CN22.6 CN23.6 CN24.6 CN25.6 U15.12 | length 856
  Top Layer w0.203: CN20.6@9.1,130.28 10.13,129.25 16.604,129.25 16.814,129.46 68.263,129.46 68.33,129.527 v1(226.182,129.527) v1(332.722,129.527) 383.54,129.527 383.762,129.305 390.236,129.305 CN25.6@391.265,130.335 ; U15.12@231.275,114.87 231.275,115.913 231.782,116.421 v1(231.782,117.679) ; v1(331.925,17.333) 332.259,16.999 332.259,13.945 332.26,13.944 332.26,13 333.288,11.972 CN22.6@333.288,11.923
  Bottom Layer w0.203: v1(119.862,129.527) 120.862,130.527 120.862,232.749 121.43,233.316 121.43,239.79 CN23.6@120.4,240.82 ; CN21.6@226.72,240.82 227.75,239.79 227.75,233.316 227.182,232.749 227.182,130.527 v1(226.182,129.527) 226.182,125.818 231.782,120.218 v1(231.782,117.679) ; v1(331.925,17.333) 331.889,17.369 331.889,36 331.889,128.694 v1(332.722,129.527) 333.722,130.527 333.722,232.749 334.29,233.316 334.29,239.79 CN24.6@333.26,240.82
H1-7: CN20.7 CN21.7 CN22.7 CN23.7 CN24.7 CN25.7 U15.14 | length 865.8
  Top Layer w0.203: v1(18.478,131.333) v1(117.904,131.333) v1(224.323,131.333) v1(330.764,131.333) 362.403,131.333 362.489,131.419 381.875,131.419 v1(381.887,131.43) ; CN23.7@117.86,243.54 118.95,242.45 118.95,235.278 119.347,234.881 119.347,232.216 118.904,231.774 v1(118.904,230.349) ; CN21.7@224.18,243.54 225.27,242.45 225.27,235.3 225.667,234.903 225.667,232.216 225.224,231.774 v1(225.224,230.349) ; U15.14@229.975,114.87 229.975,115.913 230.482,116.421 v1(230.482,117.679) ; CN24.7@330.72,243.54 331.81,242.45 331.81,235.336 332.207,234.94 332.207,232.216 331.764,231.774 v1(331.764,230.349)
  Bottom Layer w0.203: CN20.7@6.38,132.82 7.47,131.73 14.601,131.73 14.895,131.436 17.413,131.436 17.515,131.333 v1(18.478,131.333) ; v1(117.904,131.333) 118.904,132.333 v1(118.904,230.349) ; v1(225.224,230.349) 225.224,132.333 225.224,132.235 v1(224.323,131.333) 224.323,125.677 230.482,119.518 v1(230.482,117.679) ; CN22.7@330.748,14.463 330,15.212 330,130.569 v1(330.764,131.333) 331.764,132.333 v1(331.764,230.349) ; v1(381.887,131.43) 381.929,131.388 385.368,131.388 385.765,131.785 392.895,131.785 CN25.7@393.985,132.875
H1-8: CN20.8 CN21.8 CN22.8 CN23.8 CN24.8 CN25.8 U15.15 | length 853.6
  Top Layer w0.203: CN20.8@9.1,132.82 10.13,131.79 16.604,131.79 16.88,132.067 v1(117.332,132.067) v1(223.789,132.067) v1(330.192,132.067) 383.54,132.067 383.762,131.845 390.236,131.845 CN25.8@391.265,132.875 ; U15.15@229.325,114.87 229.325,115.913 229.832,116.421 v1(229.832,116.994) ; v1(329.408,17.314) 329.408,17.31 329.719,16.999 329.719,13.945 329.72,13.944 329.72,13 330.748,11.972 CN22.8@330.748,11.923
  Bottom Layer w0.203: v1(117.332,132.067) 118.332,133.067 118.332,232.759 118.89,233.316 118.89,239.79 CN23.8@117.86,240.82 ; CN21.8@224.18,240.82 225.21,239.79 225.21,233.316 224.652,232.759 224.652,133.067 224.652,132.93 v1(223.789,132.067) 223.789,125.211 229.832,119.168 v1(229.832,116.994) ; v1(329.408,17.314) 329.408,131.283 v1(330.192,132.067) 331.192,133.067 331.192,232.759 331.75,233.316 331.75,239.79 CN24.8@330.72,240.82
H1-9: CN20.9 CN21.9 CN22.9 CN23.9 CN24.9 CN25.9 U15.18 | length 862.8
  Top Layer w0.203: v1(18.478,133.873) v1(115.364,133.873) v1(221.766,133.873) v1(328.224,133.873) 362.403,133.873 362.492,133.962 381.765,133.962 381.792,133.934 v1(381.887,133.934) ; CN23.9@115.32,243.54 116.41,242.45 116.41,235.319 116.807,234.923 116.807,232.216 116.364,231.774 v1(116.364,230.349) ; CN21.9@221.64,243.54 222.73,242.45 222.73,235.319 223.127,234.923 223.127,232.216 222.684,231.774 v1(222.684,230.349) ; v1(226.868,117.679) 226.868,116.421 227.375,115.913 U15.18@227.375,114.87 ; CN24.9@328.18,243.54 329.27,242.45 329.27,235.319 329.667,234.923 329.667,232.216 329.224,231.774 v1(329.224,230.349)
  Bottom Layer w0.203: CN20.9@6.38,135.36 7.47,134.27 14.601,134.27 14.997,133.873 v1(18.478,133.873) ; v1(115.364,133.873) 116.364,134.873 v1(116.364,230.349) ; v1(222.684,230.349) 222.684,134.873 221.766,133.955 v1(221.766,133.873) 221.766,124.234 226.868,119.132 v1(226.868,117.679) ; CN22.9@328.208,14.463 327.482,15.189 327.482,133.131 v1(328.224,133.873) 329.224,134.873 v1(329.224,230.349) ; v1(381.887,133.934) 381.893,133.928 385.368,133.928 385.765,134.325 392.895,134.325 CN25.9@393.985,135.415
H1-10: CN20.10 CN21.10 CN22.10 CN23.10 CN24.10 CN25.10 U15.20 | length 850.4
  Top Layer w0.203: CN20.10@9.1,135.36 10.13,134.33 16.604,134.33 16.88,134.607 v1(114.781,134.607) v1(221.232,134.607) v1(327.641,134.607) 383.54,134.607 383.762,134.385 390.236,134.385 CN25.10@391.265,135.415 ; v1(225.568,117.679) 225.568,116.421 226.075,115.913 U15.20@226.075,114.87 ; v1(326.923,17.346) 326.923,17.255 327.179,16.999 327.179,13.945 327.18,13.944 327.18,13 328.208,11.972 CN22.10@328.208,11.923
  Bottom Layer w0.203: v1(114.781,134.607) 115.781,135.607 115.781,232.747 116.35,233.316 116.35,239.79 CN23.10@115.32,240.82 ; CN21.10@221.64,240.82 222.67,239.79 222.67,233.316 222.101,232.747 222.101,135.607 222.101,135.476 v1(221.232,134.607) 221.232,123.768 225.568,119.432 v1(225.568,117.679) ; v1(326.923,17.346) 326.808,17.461 326.808,36 326.808,133.774 v1(327.641,134.607) 328.641,135.607 328.641,232.747 329.21,233.316 329.21,239.79 CN24.10@328.18,240.82
H1-11: CN20.11 CN21.11 CN22.11 CN23.11 CN24.11 CN25.11 U14.14 | length 858.9
  Top Layer w0.203: v1(18.478,136.565) 18.529,136.615 v1(112.824,136.615) v1(219.144,136.615) v1(325.684,136.615) 381.74,136.615 v1(381.887,136.468) v1@381.859,136.441 ; CN23.11@112.78,243.54 113.87,242.45 113.87,235.319 114.267,234.923 114.267,232.216 113.824,231.774 v1(113.824,230.349) ; CN21.11@219.1,243.54 220.19,242.45 220.19,235.319 220.587,234.923 220.587,232.216 220.144,231.774 v1(220.144,230.349) ; U14.14@219.975,114.87 219.975,115.913 220.482,116.421 v1(220.482,117.679) ; CN24.11@325.64,243.54 326.73,242.45 326.73,235.319 327.127,234.923 327.127,232.216 326.684,231.774 v1(326.684,230.349)
  Bottom Layer w0.203: CN20.11@6.38,137.9 7.47,136.81 14.601,136.81 14.997,136.413 16.621,136.413 16.772,136.565 v1(18.478,136.565) ; v1(112.824,136.615) 113.824,137.615 v1(113.824,230.349) ; v1(220.144,230.349) 220.144,137.615 v1(219.144,136.615) 219.144,136.533 219,136.389 219,120 220.482,118.518 v1(220.482,117.679) ; CN22.11@325.668,14.463 324.885,15.247 324.885,17.557 324.825,17.616 324.825,36 324.825,135.757 v1(325.684,136.615) 326.684,137.615 v1(326.684,230.349) ; v1(381.887,136.468) 385.368,136.468 385.765,136.865 392.895,136.865 CN25.11@393.985,137.955
H1-12: CN20.12 CN21.12 CN22.12 CN23.12 CN24.12 CN25.12 U14.15 | length 846.8
  Top Layer w0.203: CN20.12@8.92,137.9 9.1,137.9 10.13,136.87 16.604,136.87 16.982,137.249 v1(112.255,137.249) 218.575,137.249 v1(325.115,137.249) 383.438,137.249 383.762,136.925 390.236,136.925 CN25.12@391.265,137.955 ; U14.15@219.325,114.87 219.325,115.913 219.832,116.421 v1(219.832,116.994) ; v1(324.305,17.333) 324.639,16.999 324.639,13.945 324.64,13.944 324.64,13 325.668,11.972 CN22.12@325.668,11.923
  Bottom Layer w0.203: v1(112.255,137.249) 113.255,138.249 113.255,232.762 113.81,233.316 113.81,239.79 CN23.12@112.78,240.82 ; v1@218.633,137.307 219.575,138.249 219.575,232.762 220.13,233.316 220.13,239.79 CN21.12@219.1,240.82 ; v1(218.692,137.249) 218.575,137.132 218.575,119.425 219.832,118.168 v1(219.832,116.994) ; v1(324.305,17.333) 324.224,17.414 324.224,36 324.224,136.358 v1(325.115,137.249) 326.115,138.249 326.115,232.762 326.67,233.316 326.67,239.79 CN24.12@325.64,240.82
H1-13: CN20.13 CN21.13 CN22.13 CN23.13 CN24.13 CN25.13 U14.18 | length 856
  Top Layer w0.203: v1(18.478,138.953) v1(110.284,138.953) v1(216.604,138.953) v1(323.144,138.953) 362.403,138.953 362.458,139.008 v1(381.887,139.008) v1@381.832,138.953 ; CN23.13@110.24,243.54 111.33,242.45 111.33,235.319 111.727,234.923 111.727,232.194 111.284,231.751 v1(111.284,230.326) ; CN21.13@216.56,243.54 217.65,242.45 217.65,235.319 218.047,234.923 218.047,232.194 217.604,231.751 v1(217.604,230.326) ; v1(216.868,117.679) 216.868,116.421 217.375,115.913 U14.18@217.375,114.87 ; CN24.13@323.1,243.54 324.19,242.45 324.19,235.319 324.587,234.923 324.587,232.194 324.144,231.751 v1(324.144,230.326)
  Bottom Layer w0.203: CN20.13@6.38,140.44 7.47,139.35 14.601,139.35 14.997,138.953 v1(18.478,138.953) ; v1(110.284,138.953) 111.284,139.953 v1(111.284,230.326) ; v1(216.868,117.679) 216.868,117.687 216.604,117.95 v1(216.604,138.953) 217.604,139.953 v1(217.604,230.326) ; CN22.13@323.128,14.463 322.345,15.247 322.345,17.557 322.22,17.681 322.22,36 322.22,138.029 v1(323.144,138.953) 324.144,139.953 v1(324.144,230.326) ; v1(381.887,139.008) 385.368,139.008 385.765,139.405 392.895,139.405 CN25.13@393.985,140.495
H1-14: CN20.14 CN21.14 CN22.14 CN23.14 CN24.14 CN25.14 U14.20 | length 844.8
  Top Layer w0.203: CN20.14@8.92,140.44 10.004,140.44 11.034,139.41 16.604,139.41 16.88,139.687 v1(109.707,139.687) v1(216.027,139.687) v1(322.567,139.687) 383.54,139.687 383.762,139.465 389.332,139.465 390.361,140.495 CN25.14@391.445,140.495 ; v1(215.568,117.679) 215.568,116.421 216.075,115.913 U14.20@216.075,114.87 ; v1(321.765,17.333) 322.099,16.999 322.099,13.945 322.1,13.944 322.1,13 323.128,11.972 CN22.14@323.128,11.923
  Bottom Layer w0.203: v1(109.707,139.687) 110.707,140.687 110.707,232.754 111.27,233.316 111.27,238.886 110.24,239.916 CN23.14@110.24,241 ; v1(215.568,117.679) 215.568,139.227 v1(216.027,139.687) 217.027,140.687 217.027,232.754 217.59,233.316 217.59,238.886 216.56,239.916 CN21.14@216.56,241 ; v1(321.765,17.333) 321.567,17.531 321.567,36 321.567,138.687 v1(322.567,139.687) 323.567,140.687 323.567,232.754 324.13,233.316 324.13,238.886 323.1,239.916 CN24.14@323.1,241
H1-15: CN20.15 CN21.15 CN22.15 CN23.15 CN24.15 CN25.15 U11.14 | length 854.8
  Top Layer w0.203: v1(18.478,141.534) 18.497,141.552 18.734,141.552 18.75,141.567 v1(107.744,141.567) v1(214.064,141.567) v1(320.604,141.567) 320.605,141.566 381.869,141.566 v1(381.887,141.548) ; CN23.15@107.7,243.54 108.79,242.45 108.79,235.319 109.187,234.923 109.187,232.157 108.744,231.715 v1(108.744,230.29) ; U11.14@209.975,114.87 209.975,115.913 210.482,116.421 v1(210.482,117.679) ; CN21.15@214.02,243.54 215.11,242.45 215.11,235.319 215.507,234.923 215.507,232.157 215.064,231.715 v1(215.064,230.29) ; CN24.15@320.56,243.54 321.65,242.45 321.65,235.319 322.047,234.923 322.047,232.157 321.604,231.715 v1(321.604,230.29)
  Bottom Layer w0.203: CN20.15@6.38,142.98 7.47,141.89 14.601,141.89 14.997,141.493 18.438,141.493 v1(18.478,141.534) ; v1(107.744,141.567) 108.744,142.567 v1(108.744,230.29) ; v1(210.482,117.679) 210.482,137.986 v1(214.064,141.567) 215.064,142.567 v1(215.064,230.29) ; CN22.15@320.588,14.463 320.588,14.61 319.625,15.573 319.625,17.552 319.604,17.573 319.604,36 319.604,140.567 v1(320.604,141.567) 321.604,142.567 v1(321.604,230.29) ; v1(381.887,141.548) 385.368,141.548 385.765,141.945 392.895,141.945 CN25.15@393.985,143.035
H1-16: CN20.16 CN21.16 CN22.16 CN23.16 CN24.16 CN25.16 U11.15 | length 843.7
  Top Layer w0.203: CN20.16@8.92,142.98 10.004,142.98 11.034,141.95 16.604,141.95 16.88,142.227 v1(107.123,142.227) v1(213.443,142.227) v1(319.983,142.227) 383.54,142.227 383.762,142.005 389.332,142.005 390.361,143.035 CN25.16@391.445,143.035 ; U11.15@209.325,114.87 209.325,115.913 209.832,116.421 v1(209.832,116.994) ; v1(319.092,17.331) 319.227,17.331 319.559,16.999 319.559,13.945 319.56,13.944 319.56,13 320.588,11.972 CN22.16@320.588,11.923
  Bottom Layer w0.203: v1(107.123,142.227) 108.123,143.227 108.123,232.71 108.73,233.316 108.73,238.886 107.7,239.916 CN23.16@107.7,241 ; v1(209.832,116.994) 209.832,138.616 v1(213.443,142.227) 214.443,143.227 214.443,232.71 215.05,233.316 215.05,238.886 214.02,239.916 CN21.16@214.02,241 ; v1(319.092,17.331) 319.045,17.378 319.045,17.56 319,17.605 319,141.244 v1(319.983,142.227) 320.983,143.227 320.983,232.71 321.59,233.316 321.59,238.886 320.56,239.916 CN24.16@320.56,241
H1-17: CN20.17 CN21.17 CN22.17 CN23.17 CN24.17 CN25.17 U11.18 | length 852.6
  Top Layer w0.203: v1(18.478,144.12) 18.537,144.179 18.681,144.179 18.713,144.21 v1(105.179,144.21) v1(211.499,144.21) v1(318.039,144.21) 362.403,144.21 362.5,144.113 v1(381.887,144.113) ; CN23.17@105.135,243.54 106.25,242.425 106.25,235.319 106.622,234.948 106.622,232.154 106.179,231.711 v1(106.179,230.286) ; v1(206.868,117.679) 206.868,116.421 207.375,115.913 U11.18@207.375,114.87 ; CN21.17@211.455,243.54 212.57,242.425 212.57,235.319 212.942,234.948 212.942,232.154 212.499,231.711 v1(212.499,230.286) ; CN24.17@317.995,243.54 319.11,242.425 319.11,235.319 319.482,234.948 319.482,232.154 319.039,231.711 v1(319.039,230.286)
  Bottom Layer w0.203: CN20.17@6.38,145.545 7.495,144.43 14.601,144.43 14.972,144.058 16.653,144.058 16.715,144.12 v1(18.478,144.12) ; v1(105.179,144.21) 106.179,145.21 v1(106.179,230.286) ; v1(206.868,117.679) 206.868,139.579 v1(211.499,144.21) 212.499,145.21 v1(212.499,230.286) ; CN22.17@318.048,14.463 317.039,15.472 317.039,36 317.039,143.21 v1(318.039,144.21) 319.039,145.21 v1(319.039,230.286) ; v1(381.887,144.113) 385.393,144.113 385.765,144.485 392.87,144.485 CN25.17@393.985,145.6
H1-18: CN20.18 CN21.18 CN22.18 CN23.18 CN24.18 CN25.18 U11.20 | length 841.8
  Top Layer w0.203: CN20.18@8.92,145.52 10.004,145.52 11.034,144.49 16.604,144.49 16.947,144.834 v1(104.632,144.834) v1(210.952,144.834) v1(317.492,144.834) 383.473,144.834 383.762,144.545 389.332,144.545 390.361,145.575 CN25.18@391.445,145.575 ; v1(205.568,117.679) 205.568,116.421 206.075,115.913 U11.20@206.075,114.87 ; v1(316.506,17.333) 316.51,17.329 316.685,17.329 316.952,17.062 316.952,13.068 318.048,11.972 CN22.18@318.048,11.923
  Bottom Layer w0.203: v1(104.632,144.834) 105.632,145.834 105.632,232.759 106.19,233.316 106.19,238.886 105.16,239.916 CN23.18@105.16,241 ; v1(205.568,117.679) 205.568,139.45 v1(210.952,144.834) 211.952,145.834 211.952,232.759 212.51,233.316 212.51,238.886 211.48,239.916 CN21.18@211.48,241 ; v1(316.506,17.333) 316.492,17.347 316.492,36 316.492,143.834 v1(317.492,144.834) 318.492,145.834 318.492,232.759 319.05,233.316 319.05,238.886 318.02,239.916 CN24.18@318.02,241
H1-19: CN20.19 CN21.19 CN22.19 CN23.19 CN24.19 CN25.19 U10.14 | length 849.8
  Top Layer w0.203: v1(18.478,146.573) v1(102.664,146.573) v1(208.984,146.573) v1(315.524,146.573) 381.832,146.573 v1(381.887,146.628) ; CN23.19@102.62,243.54 103.71,242.45 103.71,235.319 104.107,234.923 104.107,232.172 103.664,231.729 v1(103.664,230.304) ; U10.14@104.975,114.87 104.975,115.913 105.482,116.421 v1(105.482,117.679) ; CN21.19@208.94,243.54 210.03,242.45 210.03,235.319 210.427,234.923 210.427,232.172 209.984,231.729 v1(209.984,230.304) ; CN24.19@315.48,243.54 316.57,242.45 316.57,235.319 316.967,234.923 316.967,232.172 316.524,231.729 v1(316.524,230.304)
  Bottom Layer w0.203: CN20.19@6.38,148.06 7.47,146.97 14.601,146.97 14.997,146.573 v1(18.478,146.573) ; v1(103.664,230.304) 103.664,147.573 v1(102.664,146.573) 102.156,146.065 102.156,123.533 105.482,120.206 v1(105.482,117.679) ; v1(208.984,146.573) 209.984,147.573 v1(209.984,230.304) ; CN22.19@315.508,14.463 314.524,15.447 314.524,36 314.524,145.573 v1(315.524,146.573) 316.524,147.573 v1(316.524,230.304) ; v1(381.887,146.628) 385.368,146.628 385.765,147.025 392.895,147.025 CN25.19@393.985,148.115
